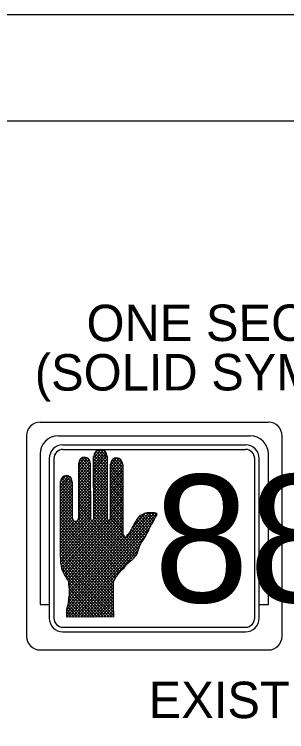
# Model space of a CAD drawing. Extents: x 662183 to 663183, y 642099 to 642739.
# Drawn here: x 662389.2 to 662419, y 642660.6 to 642739.3 of the extents above; entities that cross this region are included whole.
import ezdxf

# ---------------------------------------------------------------- set-up
doc = ezdxf.new("R2010")
doc.units = 0
for name, color, linetype in [('Default', 7, 'Continuous'), ('R_Border', 7, 'Continuous'), ('R_No Plot', 7, 'Continuous'), ('T_Drafting', 7, 'Continuous')]:
    doc.layers.add(name, color=color, linetype=linetype)

msp = doc.modelspace()

# ---------------------------------------------------------------- linework, layer by layer
at = {"layer": 'R_Border'}
msp.add_line((662219.863, 642727.616), (663168.403, 642727.616), dxfattribs=at)
at = {"layer": 'R_No Plot'}
msp.add_line((662182.661, 642739.3), (663182.661, 642739.3), dxfattribs=at)
msp.add_lwpolyline([(662182.641, 642739.3), (663182.661, 642739.3), (663182.661, 642099.287), (662182.641, 642099.287)], close=True, dxfattribs=at)
at = {"layer": 'T_Drafting'}
for p, q in [((662391.987, 642694.563), (662416.987, 642694.563)), ((662390.487, 642693.063), (662390.487, 642671.063)), ((662393.987, 642693.063), (662414.987, 642693.063)), ((662418.487, 642671.063), (662418.487, 642693.063)), ((662394.487, 642692.063), (662414.487, 642692.063)), ((662391.987, 642691.063), (662391.987, 642674.563)), ((662394.487, 642691.563), (662414.487, 642691.563)), ((662397.851, 642690.647), (662398.673, 642691.56)), ((662397.851, 642690.294), (662398.916, 642691.477)), ((662397.852, 642689.941), (662399.101, 642691.328)), ((662397.852, 642689.588), (662399.235, 642691.124)), ((662397.866, 642690.922), (662399.316, 642689.311)), ((662397.904, 642691.06), (662398.306, 642691.506)), ((662397.956, 642691.175), (662399.315, 642689.665)), ((662398.102, 642691.366), (662399.315, 642690.019)), ((662398.298, 642691.502), (662399.315, 642690.373)), ((662398.559, 642691.566), (662399.314, 642690.727)), ((662399.025, 642691.401), (662399.167, 642691.244)), ((662416.987, 642674.563), (662416.987, 642691.063)), ((662392.987, 642690.563), (662392.987, 642673.063)), ((662393.487, 642690.563), (662393.487, 642673.063)), ((662396.213, 642689.887), (662396.95, 642690.706)), ((662396.213, 642689.534), (662397.182, 642690.611)), ((662396.213, 642689.181), (662397.35, 642690.444)), ((662396.214, 642688.828), (662397.459, 642690.212)), ((662396.248, 642690.245), (662397.487, 642688.868)), ((662396.27, 642690.304), (662396.581, 642690.65)), ((662396.365, 642690.468), (662397.487, 642689.222)), ((662396.54, 642690.627), (662397.486, 642689.576)), ((662396.782, 642690.712), (662397.486, 642689.93)), ((662397.207, 642690.593), (662397.376, 642690.405)), ((662397.858, 642683.962), (662397.851, 642690.789)), ((662397.851, 642690.585), (662399.316, 642688.957)), ((662397.851, 642690.231), (662399.317, 642688.603)), ((662397.852, 642689.234), (662399.31, 642690.854)), ((662397.853, 642688.881), (662399.314, 642690.505)), ((662397.853, 642688.528), (662399.315, 642690.152)), ((662399.314, 642690.808), (662399.322, 642684.03)), ((662399.681, 642689.852), (662400.387, 642690.636)), ((662399.681, 642689.499), (662400.644, 642690.568)), ((662399.682, 642689.146), (662400.833, 642690.425)), ((662399.682, 642688.793), (662400.968, 642690.222)), ((662399.758, 642690.234), (662401.043, 642688.806)), ((662399.896, 642690.434), (662401.043, 642689.16)), ((662400.088, 642690.574), (662401.042, 642689.513)), ((662400.35, 642690.636), (662401.042, 642689.867)), ((662415.487, 642673.063), (662415.487, 642690.563)), ((662415.987, 642673.063), (662415.987, 642690.563)), ((662396.219, 642684.09), (662396.213, 642690.055)), ((662396.213, 642689.93), (662397.487, 642688.514)), ((662396.213, 642689.576), (662397.488, 642688.16)), ((662396.214, 642688.475), (662397.486, 642689.888)), ((662396.215, 642688.122), (662397.486, 642689.535)), ((662397.485, 642690.041), (662397.492, 642683.995)), ((662397.852, 642689.877), (662399.317, 642688.249)), ((662397.852, 642689.523), (662399.317, 642687.895)), ((662397.854, 642688.175), (662399.315, 642689.799)), ((662397.854, 642687.822), (662399.316, 642689.446)), ((662399.688, 642683.998), (662399.681, 642689.946)), ((662399.681, 642689.612), (662401.044, 642688.098)), ((662399.683, 642689.964), (662401.044, 642688.452)), ((662399.683, 642688.44), (662401.04, 642689.947)), ((662399.683, 642688.086), (662401.042, 642689.597)), ((662401.042, 642689.899), (662401.051, 642682.242)), ((662394.224, 642688.032), (662394.82, 642688.693)), ((662394.225, 642687.679), (662395.095, 642688.645)), ((662394.545, 642688.602), (662395.498, 642687.542)), ((662394.784, 642688.69), (662395.498, 642687.896)), ((662395.187, 642688.595), (662395.409, 642688.348)), ((662396.213, 642689.222), (662397.488, 642687.806)), ((662396.214, 642688.868), (662397.489, 642687.452)), ((662396.215, 642687.769), (662397.487, 642689.182)), ((662396.215, 642687.416), (662397.487, 642688.828)), ((662397.853, 642689.169), (662399.318, 642687.541)), ((662397.853, 642688.815), (662399.318, 642687.187)), ((662397.854, 642687.469), (662399.316, 642689.093)), ((662397.855, 642687.116), (662399.316, 642688.74)), ((662399.682, 642689.258), (662401.044, 642687.744)), ((662399.682, 642688.904), (662401.045, 642687.39)), ((662399.683, 642687.733), (662401.043, 642689.244)), ((662399.683, 642688.55), (662401.045, 642687.036)), ((662399.684, 642687.38), (662401.043, 642688.89)), ((662394.233, 642679.791), (662394.224, 642688.034)), ((662394.225, 642687.325), (662395.291, 642688.509)), ((662394.225, 642687.896), (662395.499, 642686.48)), ((662394.226, 642686.972), (662395.428, 642688.309)), ((662394.226, 642686.619), (662395.497, 642688.032)), ((662394.257, 642688.214), (662395.499, 642686.834)), ((662394.371, 642688.441), (662395.499, 642687.188)), ((662395.498, 642688.02), (662395.502, 642684.089)), ((662396.214, 642688.514), (662397.489, 642687.098)), ((662396.215, 642688.16), (662397.489, 642686.744)), ((662396.215, 642687.806), (662397.49, 642686.39)), ((662396.216, 642687.062), (662397.487, 642688.475)), ((662396.216, 642686.709), (662397.488, 642688.122)), ((662396.217, 642686.356), (662397.488, 642687.769)), ((662397.853, 642688.461), (662399.319, 642686.833)), ((662397.854, 642688.107), (662399.319, 642686.479)), ((662397.855, 642686.763), (662399.317, 642688.387)), ((662397.856, 642686.41), (662399.317, 642688.034)), ((662399.683, 642688.196), (662401.045, 642686.682)), ((662399.683, 642687.842), (662401.046, 642686.328)), ((662399.684, 642687.027), (662401.043, 642688.537)), ((662399.685, 642686.674), (662401.044, 642688.184)), ((662399.685, 642686.321), (662401.044, 642687.831)), ((662394.225, 642687.542), (662395.5, 642686.126)), ((662394.225, 642687.189), (662395.5, 642685.772)), ((662394.226, 642686.266), (662395.498, 642687.679)), ((662394.227, 642685.913), (662395.498, 642687.326)), ((662396.215, 642687.452), (662397.49, 642686.036)), ((662396.216, 642687.098), (662397.491, 642685.682)), ((662396.217, 642686.003), (662397.489, 642687.416)), ((662396.217, 642685.65), (662397.489, 642687.063)), ((662397.854, 642687.753), (662399.319, 642686.125)), ((662397.855, 642687.399), (662399.32, 642685.771)), ((662397.855, 642687.045), (662399.32, 642685.417)), ((662397.856, 642686.056), (662399.318, 642687.68)), ((662397.856, 642685.703), (662399.318, 642687.327)), ((662397.857, 642685.35), (662399.318, 642686.974)), ((662399.684, 642687.488), (662401.046, 642685.974)), ((662399.684, 642687.134), (662401.046, 642685.62)), ((662399.685, 642685.968), (662401.045, 642687.478)), ((662399.686, 642685.615), (662401.045, 642687.125)), ((662394.226, 642686.835), (662395.501, 642685.418)), ((662394.226, 642686.481), (662395.501, 642685.064)), ((662394.227, 642685.56), (662395.499, 642686.973)), ((662394.227, 642685.207), (662395.499, 642686.62)), ((662394.228, 642684.854), (662395.5, 642686.267)), ((662396.216, 642686.744), (662397.491, 642685.328)), ((662396.217, 642686.39), (662397.491, 642684.974)), ((662396.218, 642685.297), (662397.489, 642686.71)), ((662396.218, 642684.944), (662397.49, 642686.357)), ((662397.855, 642686.691), (662399.321, 642685.063)), ((662397.856, 642686.337), (662399.321, 642684.709)), ((662397.857, 642684.997), (662399.319, 642686.621)), ((662397.858, 642684.644), (662399.319, 642686.268)), ((662399.685, 642686.78), (662401.047, 642685.266)), ((662399.685, 642686.426), (662401.047, 642684.912)), ((662399.686, 642685.262), (662401.045, 642686.772)), ((662399.687, 642684.908), (662401.046, 642686.418)), ((662394.226, 642686.127), (662395.501, 642684.71)), ((662394.227, 642685.773), (662395.502, 642684.356)), ((662394.227, 642685.419), (662395.514, 642683.989)), ((662394.228, 642684.5), (662395.5, 642685.914)), ((662394.229, 642684.147), (662395.5, 642685.56)), ((662396.217, 642686.036), (662397.492, 642684.62)), ((662396.217, 642685.682), (662397.492, 642684.266)), ((662396.219, 642684.591), (662397.49, 642686.004)), ((662396.219, 642684.238), (662397.491, 642685.65)), ((662397.854, 642683.933), (662399.32, 642685.562)), ((662397.856, 642685.983), (662399.321, 642684.355)), ((662397.857, 642685.629), (662399.316, 642684.007)), ((662397.858, 642684.291), (662399.32, 642685.915)), ((662399.685, 642686.072), (662401.048, 642684.558)), ((662399.686, 642685.718), (662401.048, 642684.204)), ((662399.687, 642684.555), (662401.046, 642686.065)), ((662399.687, 642684.202), (662401.046, 642685.712)), ((662394.228, 642685.065), (662400.605, 642677.978)), ((662394.228, 642684.711), (662400.457, 642677.789)), ((662394.229, 642683.794), (662395.501, 642685.207)), ((662394.229, 642683.441), (662395.501, 642684.854)), ((662394.231, 642681.675), (662397.491, 642685.297)), ((662394.232, 642681.322), (662397.491, 642684.944)), ((662394.245, 642679.57), (662399.32, 642685.209)), ((662394.257, 642679.229), (662399.321, 642684.855)), ((662394.526, 642678.114), (662401.047, 642685.359)), ((662394.649, 642677.897), (662401.047, 642685.006)), ((662394.775, 642677.683), (662401.047, 642684.653)), ((662394.92, 642673.955), (662404.525, 642684.627)), ((662395.024, 642674.425), (662404.236, 642684.66)), ((662395.095, 642674.857), (662403.918, 642684.66)), ((662396.218, 642685.328), (662397.508, 642683.894)), ((662396.218, 642684.974), (662401.565, 642679.034)), ((662396.219, 642684.62), (662401.408, 642678.855)), ((662397.857, 642685.275), (662402.551, 642680.059)), ((662397.857, 642684.921), (662402.411, 642679.861)), ((662399.686, 642685.364), (662401.048, 642683.85)), ((662399.687, 642685.01), (662401.049, 642683.496)), ((662399.687, 642684.656), (662401.049, 642683.142)), ((662403.82, 642684.66), (662404.486, 642683.919)), ((662404.138, 642684.66), (662404.599, 642684.147)), ((662404.48, 642684.634), (662404.71, 642684.378)), ((662394.228, 642684.357), (662400.323, 642677.584)), ((662394.229, 642684.003), (662400.18, 642677.39)), ((662394.23, 642683.088), (662395.502, 642684.501)), ((662394.23, 642682.735), (662395.502, 642684.148)), ((662394.231, 642682.382), (662395.565, 642683.864)), ((662394.232, 642680.969), (662397.492, 642684.591)), ((662394.232, 642680.616), (662397.492, 642684.238)), ((662394.233, 642680.263), (662397.506, 642683.9)), ((662394.305, 642678.929), (662399.321, 642684.502)), ((662394.355, 642678.63), (662399.322, 642684.149)), ((662394.419, 642678.348), (662399.379, 642683.86)), ((662394.899, 642677.467), (662401.048, 642684.299)), ((662394.909, 642673.59), (662404.755, 642684.53)), ((662394.909, 642673.237), (662404.449, 642683.836)), ((662395.02, 642677.248), (662401.048, 642683.946)), ((662396.193, 642683.941), (662401.09, 642678.501)), ((662396.219, 642684.266), (662401.252, 642678.675)), ((662397.837, 642683.882), (662401.924, 642679.341)), ((662397.858, 642684.567), (662402.261, 642679.674)), ((662397.858, 642684.213), (662402.105, 642679.495)), ((662399.68, 642683.956), (662401.05, 642682.434)), ((662399.687, 642684.302), (662401.049, 642682.788)), ((662402.089, 642682.981), (662403.544, 642684.598)), ((662402.614, 642683.878), (662403.788, 642682.574)), ((662402.69, 642684.003), (662403.032, 642684.383)), ((662402.745, 642684.086), (662403.9, 642682.803)), ((662402.896, 642684.272), (662404.012, 642683.032)), ((662403.093, 642684.406), (662404.134, 642683.249)), ((662403.318, 642684.51), (662404.262, 642683.461)), ((662403.553, 642684.602), (662404.384, 642683.679)), ((662394.229, 642683.649), (662400.068, 642677.161)), ((662394.23, 642683.295), (662399.984, 642676.901)), ((662394.231, 642682.029), (662395.746, 642683.712)), ((662394.233, 642679.91), (662397.716, 642683.779)), ((662395.114, 642676.999), (662401.048, 642683.593)), ((662395.149, 642676.685), (662401.049, 642683.24)), ((662395.77, 642683.704), (662400.765, 642678.155)), ((662396.047, 642683.75), (662400.927, 642678.328)), ((662397.6, 642683.792), (662401.736, 642679.197)), ((662399.494, 642683.809), (662402.644, 642680.309)), ((662402.229, 642683.245), (662403.43, 642681.911)), ((662402.354, 642683.46), (662403.551, 642682.129)), ((662402.493, 642683.659), (662403.671, 642682.351)), ((662394.23, 642682.941), (662399.995, 642676.535)), ((662394.23, 642682.587), (662399.981, 642676.197)), ((662395.175, 642673.177), (662403.973, 642682.954)), ((662395.18, 642676.365), (662401.049, 642682.887)), ((662395.199, 642676.033), (662401.05, 642682.534)), ((662401.731, 642682.384), (662402.929, 642681.054)), ((662401.865, 642682.589), (662403.047, 642681.275)), ((662402.003, 642682.789), (662403.169, 642681.494)), ((662402.109, 642683.025), (662403.3, 642681.701)), ((662394.231, 642682.233), (662399.982, 642675.843)), ((662394.231, 642681.879), (662399.998, 642675.471)), ((662394.231, 642681.525), (662400, 642675.116)), ((662395.14, 642675.26), (662401.212, 642682.007)), ((662395.196, 642675.676), (662401.095, 642682.231)), ((662395.493, 642673.178), (662403.555, 642682.135)), ((662401.434, 642682.007), (662402.726, 642680.572)), ((662401.583, 642682.195), (662402.821, 642680.82)), ((662394.232, 642681.171), (662400, 642674.762)), ((662394.232, 642680.817), (662400, 642674.408)), ((662395.812, 642673.178), (662402.972, 642681.135)), ((662394.233, 642680.463), (662400.003, 642674.052)), ((662394.233, 642680.109), (662400.017, 642673.683)), ((662396.13, 642673.179), (662402.689, 642680.466)), ((662394.235, 642679.753), (662400.037, 642673.307)), ((662394.248, 642679.385), (662399.829, 642673.184)), ((662394.298, 642678.976), (662399.511, 642673.184)), ((662394.37, 642678.543), (662399.193, 642673.183)), ((662394.681, 642677.843), (662398.876, 642673.183)), ((662395.112, 642677.011), (662398.558, 642673.182)), ((662396.449, 642673.179), (662400.122, 642677.26)), ((662396.768, 642673.18), (662399.991, 642676.761)), ((662395.158, 642676.607), (662398.24, 642673.182)), ((662395.189, 642676.218), (662397.922, 642673.181)), ((662397.086, 642673.18), (662399.989, 642676.405)), ((662397.405, 642673.181), (662399.98, 642676.042)), ((662395.134, 642675.219), (662396.969, 642673.18)), ((662395.181, 642675.52), (662397.287, 642673.18)), ((662395.202, 642675.851), (662397.604, 642673.181)), ((662397.723, 642673.181), (662399.988, 642675.697)), ((662398.042, 642673.181), (662399.999, 642675.356)), ((662391.987, 642674.563), (662392.987, 642674.563)), ((662395.064, 642674.589), (662396.333, 642673.179)), ((662395.1, 642674.903), (662396.651, 642673.18)), ((662398.361, 642673.182), (662400, 642675.003)), ((662398.679, 642673.182), (662400, 642674.65)), ((662415.987, 642674.563), (662416.987, 642674.563)), ((662394.91, 642673.699), (662395.38, 642673.178)), ((662394.925, 642674.037), (662395.698, 642673.178)), ((662394.989, 642674.319), (662396.015, 642673.179)), ((662398.998, 642673.183), (662400, 642674.297)), ((662399.316, 642673.183), (662400.006, 642673.949)), ((662399.635, 642673.184), (662400.02, 642673.612)), ((662394.909, 642673.347), (662395.062, 642673.177)), ((662394.935, 642673.177), (662394.909, 642673.209)), ((662400.014, 642673.184), (662394.935, 642673.177)), ((662399.954, 642673.184), (662400.037, 642673.277)), ((662400.038, 642673.178), (662400.014, 642673.184)), ((662394.487, 642672.063), (662414.487, 642672.063)), ((662394.487, 642671.563), (662414.487, 642671.563)), ((662391.987, 642669.563), (662416.987, 642669.563))]:
    msp.add_line(p, q, dxfattribs=at)
for centre, radius, start, end in [((662391.987, 642693.063), 1.5, 90, 180), ((662416.987, 642693.063), 1.5, 0, 90), ((662393.987, 642691.063), 2, 90, 180), ((662414.987, 642691.063), 2, 0, 90), ((662394.487, 642690.563), 1.5, 90, 180), ((662414.487, 642690.563), 1.5, 0, 90), ((662394.487, 642690.563), 1, 90, 180), ((662414.487, 642690.563), 1, 0, 90), ((662394.487, 642673.063), 1.5, 180, 270), ((662394.487, 642673.063), 1, 180, 270), ((662414.487, 642673.063), 1.5, 270, 0), ((662414.487, 642673.063), 1, 270, 0), ((662391.987, 642671.063), 1.5, 180, 270), ((662416.987, 642671.063), 1.5, 270, 0)]:
    msp.add_arc(centre, radius, start, end, dxfattribs=at)
for centre, major_axis, start_param, end_param in [((662398.583, 642690.752), (0, -0.814), 1.640121, 4.665593), ((662396.849, 642690.007), (0, -0.709), 1.618611, 4.644084), ((662400.36, 642689.879), (0, -0.758), 1.597842, 4.623315), ((662394.861, 642687.986), (0, -0.709), 1.618611, 4.644084), ((662395.861, 642684.09), (0, -0.398), 4.713646, 7.855239), ((662397.675, 642683.978), (0, -0.204), 4.633755, 7.775348), ((662399.502, 642684.016), (0, -0.207), 4.624552, 7.766145)]:
    msp.add_ellipse(centre, major_axis=major_axis, ratio=0.9, start_param=start_param, end_param=end_param, dxfattribs=at)
for points in [[(662401.05, 642682.243), (662401.101, 642682.229), (662401.171, 642682.074), (662401.259, 642681.955), (662401.311, 642681.936), (662401.398, 642681.955), (662401.452, 642682.035), (662401.611, 642682.229), (662401.734, 642682.388), (662401.804, 642682.504), (662401.874, 642682.602), (662401.997, 642682.778), (662402.067, 642682.935), (662402.172, 642683.149), (662402.243, 642683.267), (662402.366, 642683.482), (662402.505, 642683.679), (662402.611, 642683.874), (662402.734, 642684.069), (662402.84, 642684.206), (662402.997, 642684.363), (662403.19, 642684.443), (662403.296, 642684.502), (662403.455, 642684.559), (662403.595, 642684.619), (662403.807, 642684.66), (662403.983, 642684.66), (662404.212, 642684.66), (662404.423, 642684.64), (662404.669, 642684.602), (662404.739, 642684.561), (662404.755, 642684.504), (662404.652, 642684.25), (662404.581, 642684.112), (662404.512, 642683.974), (662404.441, 642683.818), (662404.405, 642683.72), (662404.265, 642683.465), (662404.056, 642683.114), (662403.774, 642682.547), (662403.423, 642681.899), (662403.142, 642681.449), (662402.983, 642681.155), (662402.844, 642680.88), (662402.762, 642680.663), (662402.719, 642680.552), (662402.562, 642680.08), (662402.317, 642679.746), (662402.123, 642679.512), (662401.843, 642679.276), (662401.666, 642679.139), (662401.21, 642678.629), (662400.806, 642678.199), (662400.543, 642677.905), (662400.314, 642677.571), (662400.199, 642677.426), (662400.103, 642677.22), (662399.997, 642677.023), (662399.998, 642676.593), (662399.981, 642676.207), (662399.982, 642675.853), (662399.999, 642675.385), (662400, 642674.935), (662400.001, 642674.211), (662400.019, 642673.628), (662400.037, 642673.412), (662400.037, 642673.254), (662400.037, 642673.179)], [(662394.909, 642673.209), (662394.909, 642673.523), (662394.926, 642674.05), (662395.065, 642674.598), (662395.135, 642675.224), (662395.188, 642675.577), (662395.187, 642676.262), (662395.133, 642676.828), (662395.08, 642677.121), (662394.816, 642677.61), (662394.534, 642678.1), (662394.375, 642678.51), (662394.304, 642678.94), (662394.25, 642679.273), (662394.25, 642679.487), (662394.233, 642679.791)]]:
    msp.add_spline(points, degree=3, dxfattribs=at)

# ---------------------------------------------------------------- texts
at = {"layer": 'Default'}
msp.add_text('EXISTING', height=4, dxfattribs=at).set_placement((662403.873, 642662.086))
at = {"layer": 'T_Drafting'}
for s, height, p in [('ONE SECTION', 4, (662397.072, 642703.44)), ('(SOLID SYMBOL)', 4, (662391.407, 642698.015)), ('88', 14, (662404.451, 642674.784))]:
    msp.add_text(s, height=height, rotation=0.07203, dxfattribs=at).set_placement(p)

doc.saveas('drawing.dxf')
